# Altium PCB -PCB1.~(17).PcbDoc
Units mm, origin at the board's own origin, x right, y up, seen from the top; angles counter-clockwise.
Board outline 80 x 60 mm, 2 copper layers (Top Layer, Bottom Layer); 29 components, 21 nets, 66 pads, 0 vias.
Unrouted connection lines stored in the file: 1.
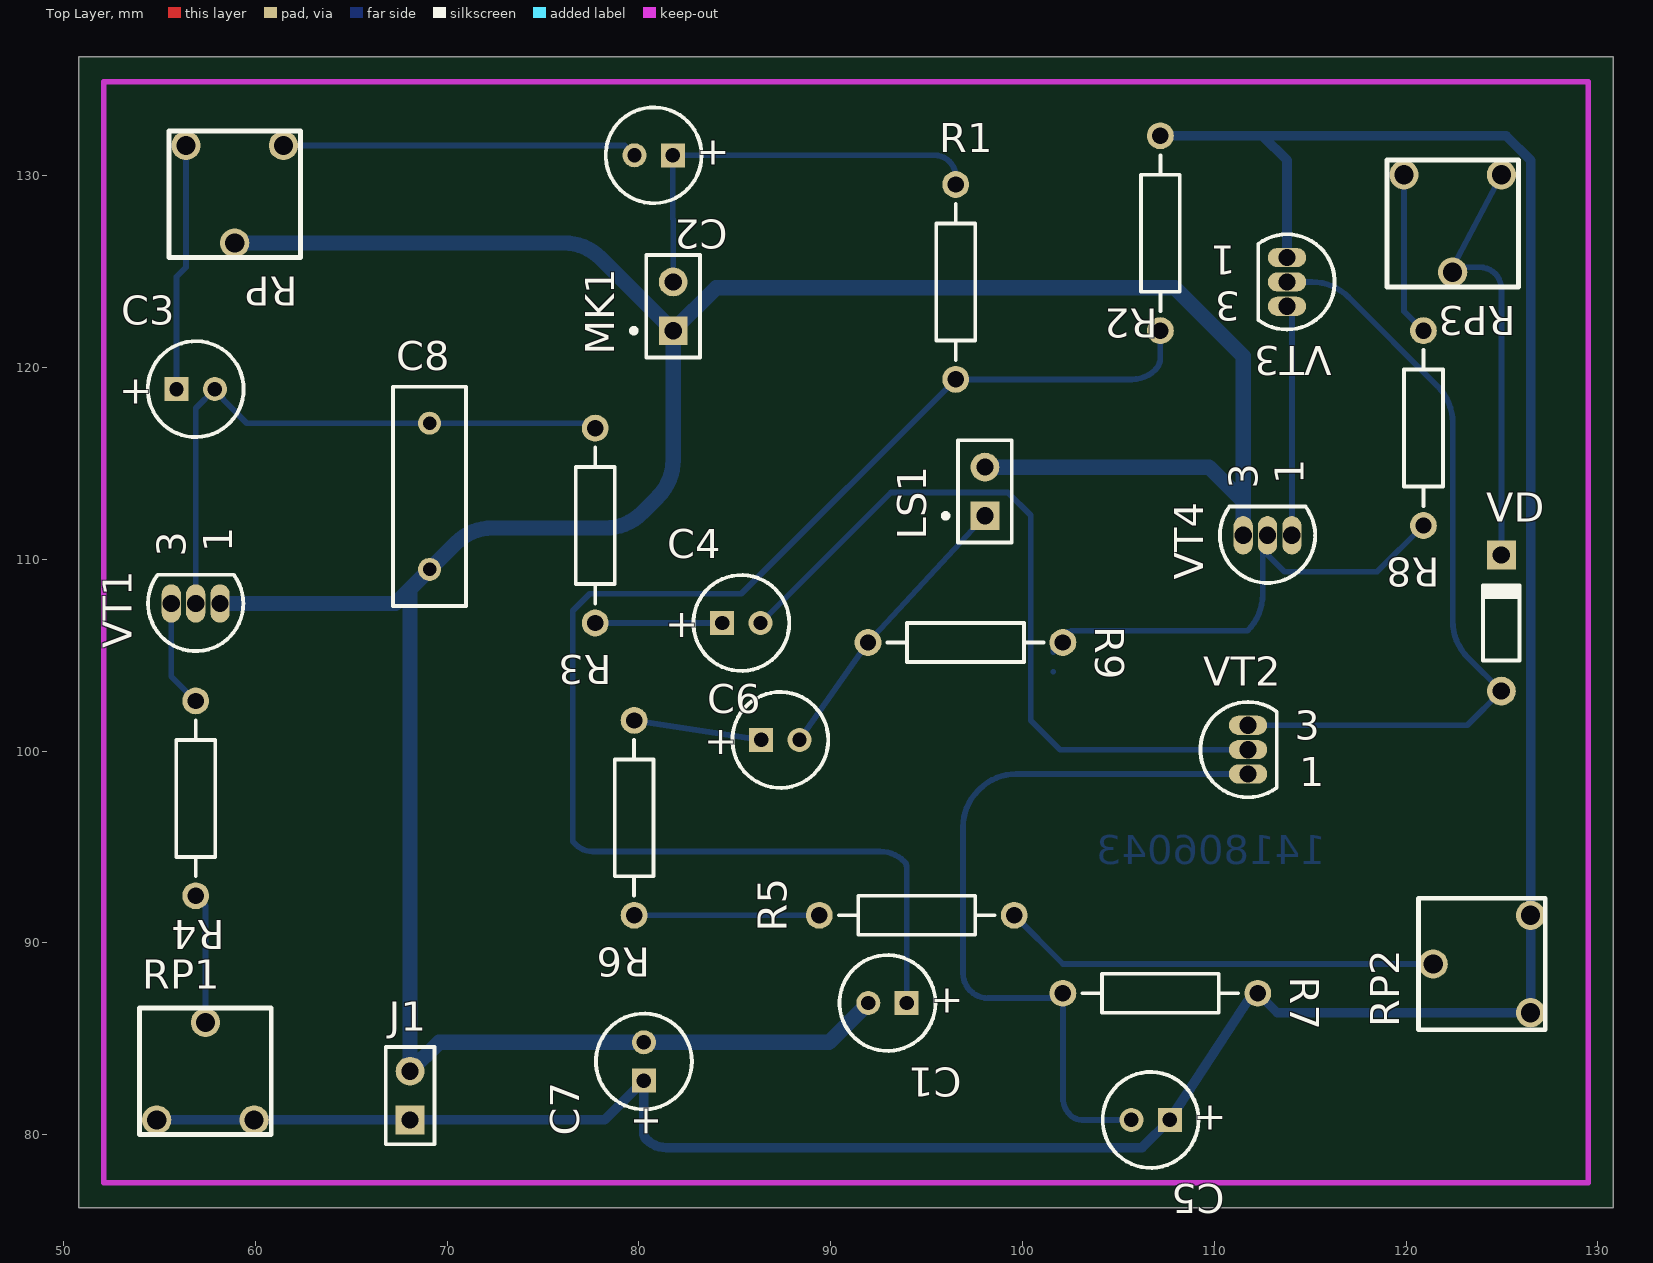
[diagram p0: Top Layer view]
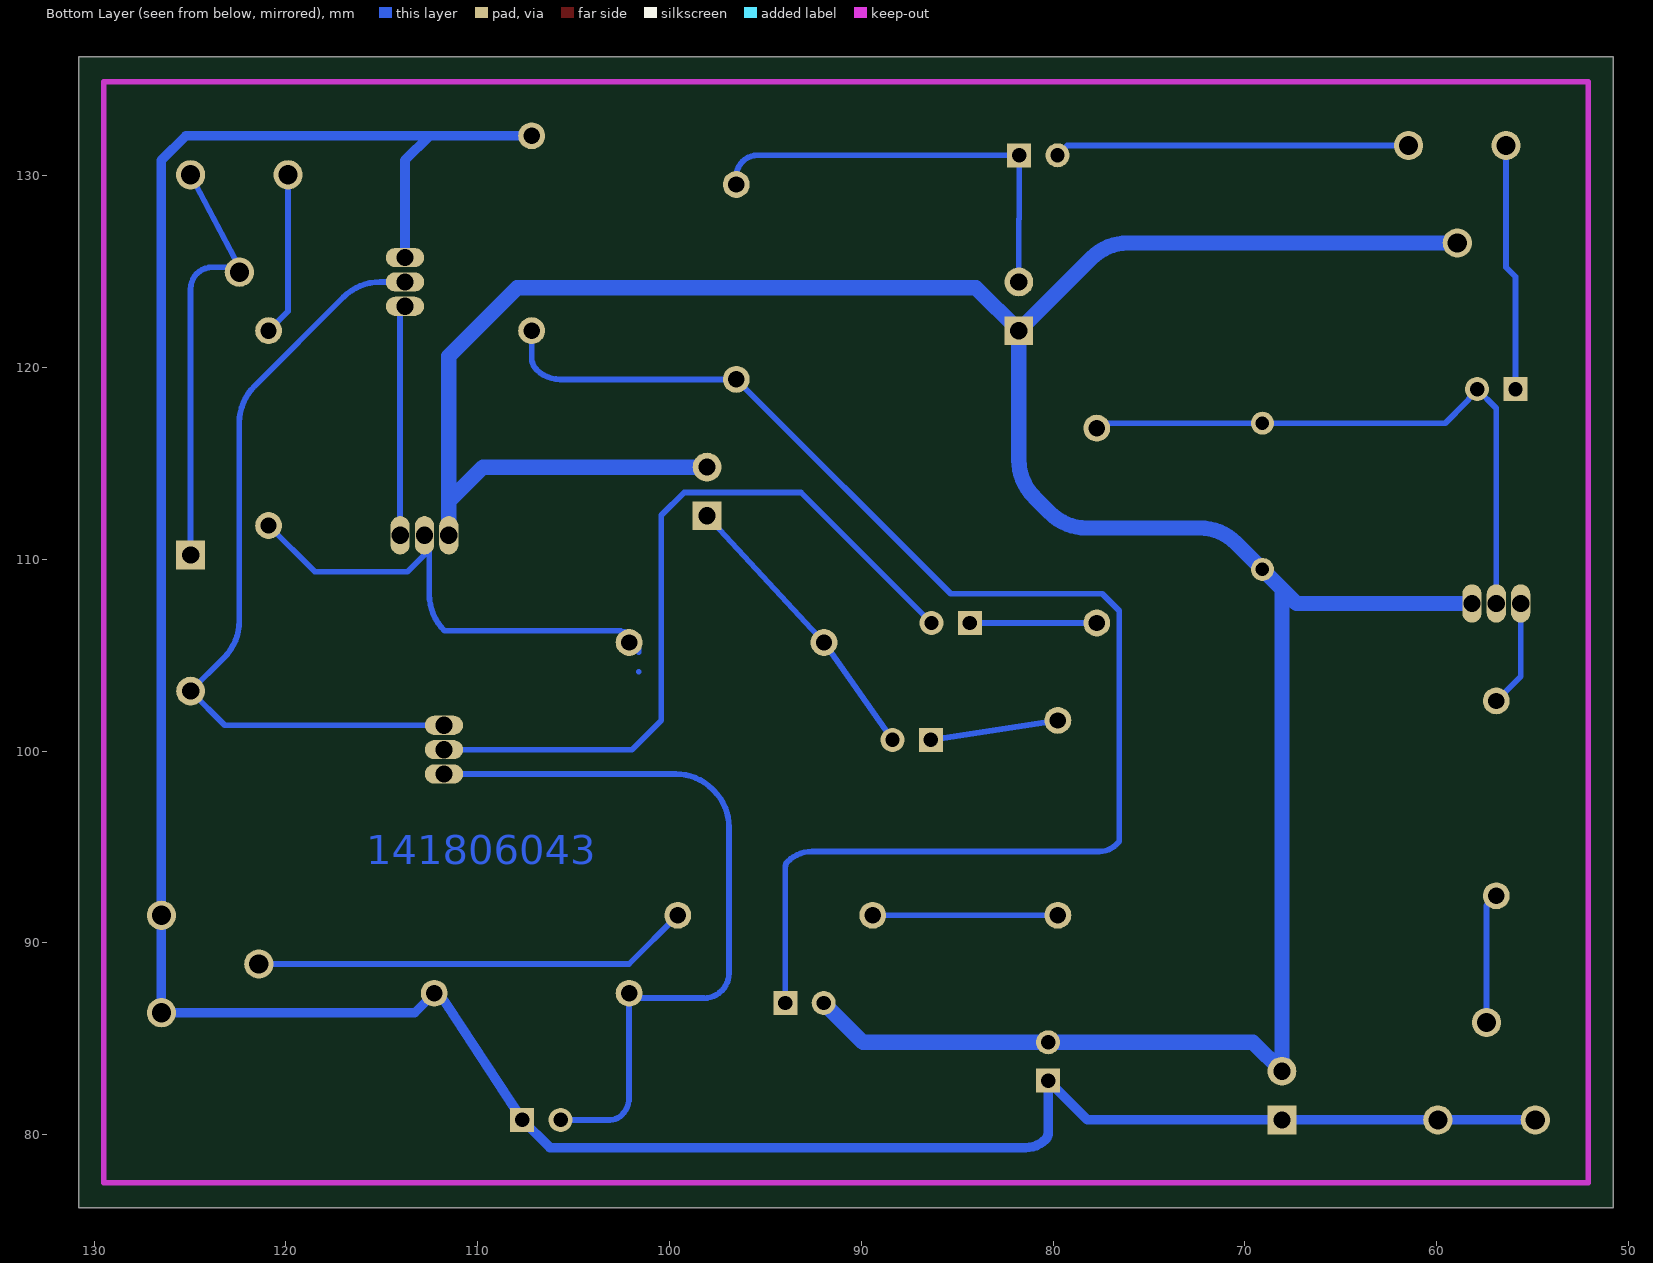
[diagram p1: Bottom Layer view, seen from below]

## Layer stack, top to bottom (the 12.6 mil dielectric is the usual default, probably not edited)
Top Layer: signal copper 0.0356
Dielectric: dielectric 0.32, FR-4, Dk 4.8
Bottom Layer: signal copper 0.0356

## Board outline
50.8,76.2 130.8,76.2 130.8,136.2 50.8,136.2

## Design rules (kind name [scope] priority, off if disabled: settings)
Clearance [All] p1: gap=0.3
ComponentClearance [All] p1: gap=0.254 collisioncheckmode=0
PolygonConnect [All] p1: connectstyle=Relief reliefconductorwidth=0.254 reliefentries=4 polygonreliefangle="90 Angle"
RoutingVias [All] p1: holewidth=0.8 width=1.8 viastyle="Through Hole" minholewidth=0.711 minwidth=1.27 maxholewidth=0.711 maxwidth=1.27
SolderMaskExpansion [All] p1: expansion=0.102
TestPointUsage [All] p1: valid=0 allowmultiple=FALSE
Testpoint [All] p1: side=15 testpointundercomponent=TRUE minsize=1.016 maxsize=2.54 preferedsize=1.524 minholesize=0 maxholesize=1.016 preferedholesize=0.813 testpointgrid=0.025 style=1023 order=1234567890
Width Width_2 [InNet('GND')] p1: maxlimit=0.8 minlimit=0.8 preferedwidth=0.8
Width Width_1 [InNet('VCC')] p2: maxlimit=0.5 minlimit=0.5 preferedwidth=0.5
Width [All] p3: maxlimit=0.3 minlimit=0.3 preferedwidth=0.3
17 further rules are at their usual default settings.

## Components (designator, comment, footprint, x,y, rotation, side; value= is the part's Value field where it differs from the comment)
C1 "Cap Pol1" CAPPR2-5x6.8 92.964,86.868 r180 top
C2 "Cap Pol1" CAPPR2-5x6.8 80.772,131.064 r180 top
C3 "Cap Pol1" CAPPR2-5x6.8 56.896,118.872 r0 top
C4 "Cap Pol1" CAPPR2-5x6.8 85.344,106.68 r0 top
C5 "Cap Pol1" CAPPR2-5x6.8 106.68,80.772 r180 top
C6 "Cap Pol1" CAPPR2-5x6.8 87.376,100.584 r0 top
C7 "Cap Pol1" CAPPR2-5x6.8 80.264,83.82 r90 top
C8 "Cap" RAD-0.3 69.088,113.284 r90 top
J1 "MHDR1X2" HDR1X2 68.072,80.772 r90 top
LS1 "Speaker" PIN2 98.044,112.268 r90 top
MK1 "Mic" PIN2 81.788,121.92 r90 top
R1 "Res2" AXIAL-0.4 96.52,124.46 r90 top
R2 "Res2" AXIAL-0.4 107.188,127 r270 top
R3 "Res2" AXIAL-0.4 77.724,111.76 r270 top
R4 "Res2" AXIAL-0.4 56.896,97.536 r270 top
R5 "Res2" AXIAL-0.4 94.488,91.44 r180 top
R6 "Res2" AXIAL-0.4 79.756,96.52 r270 top
R7 "47" AXIAL-0.4 107.188,87.376 r0 top
R8 "Res2" AXIAL-0.4 120.904,116.84 r270 top
R9 "Res2" AXIAL-0.4 97.028,105.664 r0 top
RP "RPot" RM065 58.928,129.032 r180 top
RP1 "RPot" RM065 57.404,83.312 r0 top
RP2 "RPot" RM065 123.952,88.9 r90 top
RP3 "100" RM065 122.428,127.508 r180 top
VD "4148" DIO7.1-3.9x1.9 124.968,106.68 r90 top
VT1 "9014" BCY-W3/E4 56.896,107.696 r90 top
VT2 "9015" BCY-W3/E4 111.76,100.076 r0 top
VT3 "8050" BCY-W3/E4 113.792,124.46 r180 top
VT4 "8550" BCY-W3/E4 112.776,111.252 r90 top

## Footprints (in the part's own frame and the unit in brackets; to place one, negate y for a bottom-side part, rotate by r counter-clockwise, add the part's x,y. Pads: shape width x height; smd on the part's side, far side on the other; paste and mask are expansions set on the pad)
AXIAL-0.4 [mm] "Resistor; 2 Leads"
  round 1.4 hole 0.85: 1(-5.08,0) 2(5.08,0)
  silkscreen extent -4.06,-1.02 4.06,1.02
BCY-W3/E4 [mm] "TO, Flat Index; 3 In-Line, Axial Leads; Body Dia. 4.7mm"
  oval 2x1 hole 0.9: 1(0,-1.27) 2(0,0) 3(0,1.27)
  silkscreen extent -2.48,-2.48 1.5,2.48
CAPPR2-5x6.8 [mm] "Capacitor, Electrolytic, Radial; Body 5 x 6.8 mm (Dia.xH typ); Pin Spacing 2 mm (typ)"
  rect 1.25x1.25 hole 0.75: 1(-1,0)
  round 1.25 hole 0.75: 2(1,0)
  silkscreen extent -2.5,-2.5 2.5,2.5
DIO7.1-3.9x1.9 [mm] "Diode, Axial; Body 3.8 x 1.9 mm (LxDia. max), Lead Dia. 0.53 mm (max)"
  round 1.5 hole 0.9: 1(-3.55,0)
  rect 1.5x1.5 hole 0.9: 2(3.55,0)
  silkscreen extent -1.95,-0.95 2.05,0.95
HDR1X2 [mm] "Connector; Header; 2 Position"
  rect 1.5x1.5 hole 0.9: 1(0,0)
  round 1.5 hole 0.9: 2(2.54,0)
  silkscreen extent -1.27,-1.27 3.81,1.27
PIN2 [mm] "Photosensitive Diode; 2 Leads"
  rect 1.5x1.5 hole 0.9: 1(0,0)
  round 1.5 hole 0.9: 2(2.54,0)
  silkscreen extent -1.4,-1.4 3.94,2.17
RAD-0.3 [mm] "Capacitor; 2 Leads"
  round 1.2 hole 0.7: 1(-3.81,0) 2(3.81,0)
  silkscreen extent -5.71,-1.91 5.71,1.91
RM065 [mil]
  round 60 hole 39.37: 1(100,-100) 2(0,100) 3(-100,-100)
  silkscreen extent -135,-130 135,130

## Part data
C1 C2 C3 C4 C5 C6 C7: "Polarized Capacitor (Radial)"
C8: "Capacitor"
J1: library part "Header 2", "Header, 2-Pin"
LS1: "Loudspeaker"
MK1: library part Mic2, "Microphone"
R1 R2 R3 R4 R5 R6 R8 R9: "Resistor"
R7: library part Res2, "Resistor"
RP RP1 RP2: "Potentiometer"
RP3: library part RPot, "Potentiometer"
VD: library part "Diode 1N4148", "High Conductance Fast Diode"
VT1: library part 2N3904, "NPN General Purpose Amplifier"
VT2 VT3 VT4: library part 2N3906, "PNP General Purpose Amplifier"

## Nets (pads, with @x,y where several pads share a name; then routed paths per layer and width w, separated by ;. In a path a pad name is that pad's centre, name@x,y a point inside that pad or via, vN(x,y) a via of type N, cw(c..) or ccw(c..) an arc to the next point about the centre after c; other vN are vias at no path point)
GND: C1.2 C7.2 C8.1 J1.2 LS1.2 MK1.1 RP.2 VT1.1 VT4.3 | length 164.6
  Bottom Layer w0.8: VT1.1 67.31,107.696 70.457,110.843 cw(c72.365,108.935) 72.365,111.633 78.257,111.633 ccw(c78.257,114.331) 80.165,112.423 80.998,113.256 ccw(c79.09,115.164) 81.788,115.164 MK1.1 ; RP.2 76.098,126.492 cw(c76.098,123.794) 78.006,125.702 MK1.1 ; 68.072,108.458 J1.2 69.58,84.82 C7.2 89.916,84.82 C1.2 ; LS1.2 109.728,114.808 111.506,113.03 ; VT4.3 111.506,120.599 107.95,124.155 84.023,124.155 MK1.1
NetC1_1: C1.1 R1.1 R2.2 | length 74.6
  Bottom Layer w0.3: C1.1 93.964,93.966 ccw(c93.585,93.966) 93.853,94.234 ccw(c92.565,92.946) 92.565,94.767 77.597,94.767 cw(c77.597,96.021) 76.711,95.135 76.556,95.29 76.556,107.315 77.445,108.204 85.344,108.204 R1.1 105.708,119.38 ccw(c105.708,121.114) 106.934,119.888 ccw(c106.321,120.501) 107.188,120.501 R2.2
NetC2_1: C2.1 MK1.2 R1.2 | length 22.4
  Bottom Layer w0.3: MK1.2 81.788,127.737 81.772,127.753 C2.1 95.402,131.064 cw(c95.402,129.946) 96.52,129.946 R1.2
NetC2_2: C2.2 RP.3 | length 18.5
  Bottom Layer w0.3: RP.3 79.264,131.572 C2.2
NetC3_1: C3.1 RP.1 | length 12.9
  Bottom Layer w0.3: C3.1 55.896,124.73 56.388,125.222 RP.1
NetC3_2: C3.2 C8.2 R3.1 VT1.2 | length 32.1
  Bottom Layer w0.3: VT1.2 56.896,117.872 C3.2 ; C3.2@58.166,118.872 ccw(c59.086,118.872) 58.435,118.222 59.563,117.094 77.111,117.094 cw(c77.111,116.227) R3.1
NetC4_1: C4.1 R3.2 | length 6.6
  Bottom Layer w0.3: R3.2 C4.1
NetC4_2: C4.2 VT2.2 | length 40.1
  Bottom Layer w0.3: C4.2 93.151,113.487 99.238,113.487 100.432,112.293 100.432,101.6 101.956,100.076 VT2.2
NetC5_2: C5.2 R7.1 VT2.1 | length 39.8
  Bottom Layer w0.3: C5.2 103.102,80.772 cw(c103.102,81.639) 102.489,81.026 cw(c103.409,81.946) 102.108,81.946 R7.1 cw(c101.495,87.989) 101.495,87.122 98.202,87.122 cw(c98.202,88.423) 97.282,87.503 cw(c98.202,88.423) 96.901,88.423 96.901,96.037 cw(c99.599,96.037) 97.691,97.945 97.762,98.016 cw(c99.67,96.108) 99.67,98.806 VT2.1
NetC6_1: C6.1 R6.1 | length 6.7
  Bottom Layer w0.3: R6.1 C6.1
NetC6_2: C6.2 LS1.1 R9.1 | length 15.2
  Bottom Layer w0.3: C6.2 R9.1 LS1.1
NetR4_1: R4.1 VT1.3 | length 5.6
  Bottom Layer w0.3: VT1.3 55.626,103.886 R4.1
NetR4_2: R4.2 RP1.2 | length 6.8
  Bottom Layer w0.3: R4.2 57.404,91.948 RP1.2
NetR5_1: R5.1 RP2.2 | length 22.9
  Bottom Layer w0.3: R5.1 102.108,88.9 RP2.2
NetR5_2: R5.2 R6.2 | length 9.9
  Bottom Layer w0.3: R6.2 R5.2@89.662,91.44
NetR8_1: R8.1 RP3.1 | length 8.5
  Bottom Layer w0.3: RP3.1 119.888,122.936 R8.1
NetR8_2: R8.2 R9.2 VT4.2 | length 26.3
  Bottom Layer w0.3: 101.6,105.153 cw(c102.718,105.153) 102.718,106.271 111.732,106.271 ccw(c109.824,108.179) 112.468,107.642 ccw(c109.824,108.179) 112.522,108.179 VT4.2@112.522,111.125 ; VT4.2 112.776,110.236 113.665,109.347 118.491,109.347 R8.2
NetRP3_2: RP3.2 RP3.3 VD.2 | length 22.5
  Bottom Layer w0.3: VD.2 124.968,124.104 ccw(c123.85,124.104) 123.85,125.222 122.428,125.222 RP3.3
NetVD_1: VD.1 VT2.3 VT3.2 | length 41
  Bottom Layer w0.3: VT2.3 123.184,101.346 VD.1 123.218,104.88 cw(c125.126,106.788) 122.428,106.788 122.428,117.119 ccw(c119.73,117.119) 121.638,119.027 116.995,123.67 ccw(c115.087,121.762) 115.898,124.335 ccw(c115.087,121.762) 115.087,124.46 VT3.2
NetVT3_3: VT3.3 VT4.1 | length 12.2
  Bottom Layer w0.3: VT3.3 114.046,123.19 VT4.1
VCC: C5.1 C7.1 J1.1 R2.1 R7.2 RP1.1 RP1.3 RP2.1 RP2.3 VT3.1 | length 151.2
  Bottom Layer w0.5: RP1.3 RP1.1 J1.1 78.216,80.772 C7.1 80.264,80.063 ccw(c80.698,80.063) 80.391,79.756 ccw(c81.433,80.798) 81.433,79.324 106.232,79.324 C5.1 111.529,86.637 R7.2@112.014,87.376 ; R2.1 112.522,132.08 ; R7.2@112.141,87.249 R7.2 113.284,86.36 RP2.3 RP2.1 126.492,130.81 125.222,132.08 112.522,132.08 ; VT3.1 113.792,130.81 112.522,132.08

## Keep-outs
Keep-Out Layer:
  lines w0.3: 52.1,77.5 52.1,134.9 129.5,134.9 129.5,77.5 52.1,77.5

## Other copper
Bottom Layer:
  text "141806043" at 115.824,94.107 h1.52

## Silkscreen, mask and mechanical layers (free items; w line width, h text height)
Drill Drawing:
  text ".LEGEND" at 135.88,81.28 h1.52
  text "Drill Drawing." at 135.88,78.74 h1.52

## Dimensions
52.1,77.5 to 52.1,134.9 on Mechanical 1
52.1,77.5 to 129.5,77.5 on Mechanical 1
